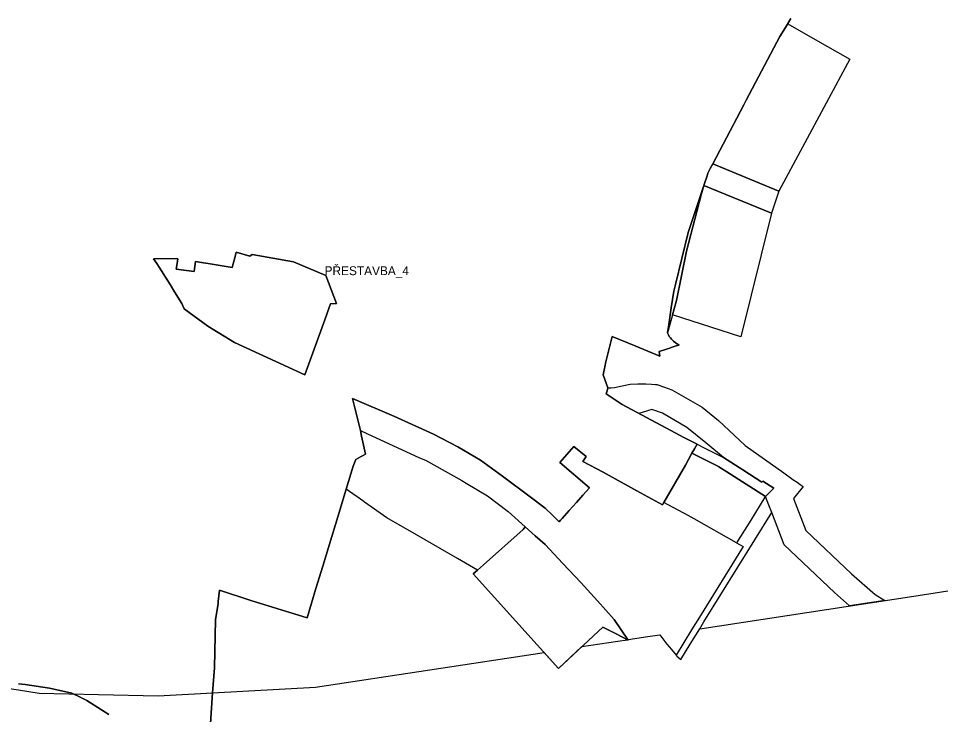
# Model space of a CAD drawing. Extents: x -521621 to -516761, y -1190184 to -1184927.
# Drawn here: x -518849 to -518120, y -1187593 to -1187044 of the extents above; entities that cross this region are included whole.
import ezdxf

# ---------------------------------------------------------------- set-up
doc = ezdxf.new("R2010")
doc.units = 0
for name, color, linetype in [('hran_SZUO_P-s', 7, 'Continuous'), ('HZU_P_s', 7, 'Continuous'), ('Implicitní', 7, 'Continuous'), ('prestavba_n', 7, 'Continuous'), ('zastavitelne plochy', 7, 'Continuous')]:
    doc.layers.add(name, color=color, linetype=linetype)

msp = doc.modelspace()

# ---------------------------------------------------------------- linework, layer by layer
at = {"layer": 'hran_SZUO_P-s'}
for points in [[(-518243.83, -1187051.46), (-518239.49, -1187044.29)], [(-518248.17, -1187058.62), (-518243.83, -1187051.46)], [(-518274.71, -1187108.86), (-518248.17, -1187058.62)], [(-518301.26, -1187159.09), (-518276.6, -1187112.43)], [(-518276.6, -1187112.43), (-518274.71, -1187108.86)], [(-518305.03, -1187166.24), (-518303.14, -1187162.67), (-518301.26, -1187159.09)], [(-518307.79, -1187174.55), (-518305.73, -1187168.34)], [(-518305.73, -1187168.34), (-518305.03, -1187166.24)], [(-518320.62, -1187213.04), (-518307.79, -1187174.55)], [(-518330.73, -1187254.09), (-518320.62, -1187213.04)], [(-518333.93, -1187272.52), (-518331.95, -1187259.37)], [(-518331.95, -1187259.37), (-518330.73, -1187254.09)], [(-518335.9, -1187285.67), (-518333.93, -1187272.52)], [(-518336.41, -1187289.03), (-518335.9, -1187285.67)], [(-518385.89, -1187316.34), (-518380.6, -1187295.26)], [(-518380.6, -1187295.26), (-518361.84, -1187302.95), (-518343.07, -1187310.63)], [(-518336.91, -1187292.39), (-518336.41, -1187289.03)], [(-518335.51, -1187295.27), (-518336.21, -1187293.83), (-518336.91, -1187292.39)], [(-518333.85, -1187297.41), (-518334.68, -1187296.34), (-518335.51, -1187295.27)], [(-518332.26, -1187298.84), (-518333.85, -1187297.41)], [(-518332.45, -1187303.46), (-518329.99, -1187302.65)], [(-518330.67, -1187300.27), (-518332.26, -1187298.84)], [(-518329.42, -1187301), (-518330.67, -1187300.27)], [(-518329.99, -1187302.65), (-518327.83, -1187301.94)], [(-518327.83, -1187301.94), (-518329.42, -1187301)], [(-518343.61, -1187307.03), (-518338.64, -1187305.49)], [(-518343.07, -1187310.63), (-518343.61, -1187307.03)], [(-518338.64, -1187305.49), (-518336.9, -1187304.92)], [(-518336.9, -1187304.92), (-518335.15, -1187304.35)], [(-518335.15, -1187304.35), (-518333.95, -1187303.95)], [(-518333.95, -1187303.95), (-518332.45, -1187303.46)], [(-518387.83, -1187325.37), (-518386.21, -1187317.82)], [(-518386.21, -1187317.82), (-518385.89, -1187316.34)], [(-518383.99, -1187335.74), (-518387.83, -1187325.37)], [(-518385.35, -1187340.38), (-518384.67, -1187338.06)], [(-518384.67, -1187338.06), (-518383.99, -1187335.74)], [(-518579.45, -1187369.29), (-518585.54, -1187344.09)], [(-518585.54, -1187344.09), (-518553.06, -1187357.95)], [(-518379.07, -1187344.6), (-518385.35, -1187340.38)], [(-518372.79, -1187348.81), (-518379.07, -1187344.6)], [(-518353.56, -1187359.03), (-518372.79, -1187348.81)], [(-518553.06, -1187357.95), (-518521.58, -1187372.14)], [(-518334.34, -1187369.25), (-518353.56, -1187359.03)], [(-518575.31, -1187388.01), (-518576.35, -1187383.33), (-518577.38, -1187378.65), (-518578.42, -1187373.97), (-518579.45, -1187369.29)], [(-518521.58, -1187372.14), (-518502.51, -1187382.22)], [(-518323.96, -1187374.76), (-518334.34, -1187369.25)], [(-518313.58, -1187380.27), (-518323.96, -1187374.76)], [(-518502.51, -1187382.22), (-518484.67, -1187392.87)], [(-518421.85, -1187394.65), (-518410.85, -1187382.12)], [(-518410.85, -1187382.12), (-518401.08, -1187389.94)], [(-518315.64, -1187383.75), (-518313.58, -1187380.27)], [(-518581.16, -1187391.1), (-518579.21, -1187390.07)], [(-518579.21, -1187390.07), (-518577.26, -1187389.04), (-518575.31, -1187388.01)], [(-518401.08, -1187389.94), (-518403.75, -1187393.75)], [(-518320.4, -1187392.2), (-518317.7, -1187387.23)], [(-518317.7, -1187387.23), (-518315.64, -1187383.75)], [(-518590.56, -1187415.7), (-518585.12, -1187397.38)], [(-518585.12, -1187397.38), (-518583.11, -1187392.13)], [(-518583.11, -1187392.13), (-518581.16, -1187391.1)], [(-518484.67, -1187392.87), (-518467.26, -1187405.28)], [(-518398.55, -1187414.52), (-518421.85, -1187394.65)], [(-518403.75, -1187393.75), (-518387.67, -1187402.29)], [(-518339.96, -1187426.08), (-518322.79, -1187396.6)], [(-518322.79, -1187396.6), (-518320.4, -1187392.2)], [(-518467.26, -1187405.28), (-518445.26, -1187421.79)], [(-518387.67, -1187402.29), (-518383.04, -1187404.83)], [(-518383.04, -1187404.83), (-518361.11, -1187416.86)], [(-518603.76, -1187459.07), (-518597.16, -1187437.39), (-518590.56, -1187415.7)], [(-518408.9, -1187426.17), (-518403.73, -1187420.34), (-518398.55, -1187414.52)], [(-518361.11, -1187416.86), (-518341.01, -1187427.89)], [(-518445.26, -1187421.79), (-518433.48, -1187430.64)], [(-518420.15, -1187438.82), (-518414.53, -1187432.5), (-518408.9, -1187426.17)], [(-518341.01, -1187427.89), (-518339.96, -1187426.08)], [(-518433.48, -1187430.64), (-518427.95, -1187436.01)], [(-518427.95, -1187436.01), (-518422.42, -1187441.37)], [(-518422.42, -1187441.37), (-518421.29, -1187440.09)], [(-518421.29, -1187440.09), (-518420.15, -1187438.82)], [(-518449.21, -1187445.4), (-518450.9, -1187447.42), (-518482.3, -1187475.38), (-518487.02, -1187479.58), (-518490.29, -1187482.49), (-518423, -1187557.03), (-518391.64, -1187528.05), (-518388.01, -1187524.58), (-518377.94, -1187529.66), (-518367.87, -1187534.73), (-518373.51, -1187526.55), (-518379.14, -1187518.37), (-518392.26, -1187503.79), (-518405.37, -1187489.2), (-518419.49, -1187474.31), (-518433.61, -1187459.42), (-518441.41, -1187452.41), (-518449.21, -1187445.4)], [(-518614.48, -1187493.95), (-518609.12, -1187476.51), (-518603.76, -1187459.07)], [(-518691.72, -1187504.38), (-518690.72, -1187495.41)], [(-518690.72, -1187495.41), (-518665.87, -1187503.51)], [(-518617.99, -1187505.53), (-518614.48, -1187493.95)], [(-518693.77, -1187518.41), (-518691.62, -1187506.18)], [(-518691.62, -1187506.18), (-518691.72, -1187504.38)], [(-518665.87, -1187503.51), (-518621.5, -1187517.1)], [(-518621.5, -1187517.1), (-518617.99, -1187505.53)], [(-518694.65, -1187556.56), (-518693.77, -1187518.41)], [(-518696.09, -1187576.42), (-518694.65, -1187556.56)], [(-518849.36, -1187569.22), (-518844.12, -1187569.84)], [(-518844.12, -1187569.84), (-518824.83, -1187572.77)], [(-518824.83, -1187572.77), (-518807.23, -1187576.63)], [(-518807.23, -1187576.63), (-518801.29, -1187579.56), (-518795.35, -1187582.49)], [(-518698.12, -1187604.41), (-518696.09, -1187576.42)], [(-518795.35, -1187582.49), (-518786.71, -1187587.97)], [(-518786.71, -1187587.97), (-518778.06, -1187593.45)]]:
    msp.add_lwpolyline(points, dxfattribs=at)
at = {"layer": 'HZU_P_s'}
for p, q in [((-518239.49, -1187044.29), (-518243.83, -1187051.46)), ((-518243.83, -1187051.46), (-518248.17, -1187058.62)), ((-518248.17, -1187058.62), (-518274.71, -1187108.86)), ((-518276.6, -1187112.43), (-518301.26, -1187159.09)), ((-518274.71, -1187108.86), (-518276.6, -1187112.43)), ((-518303.14, -1187162.67), (-518305.03, -1187166.24)), ((-518301.26, -1187159.09), (-518303.14, -1187162.67)), ((-518305.73, -1187168.34), (-518307.79, -1187174.55)), ((-518305.03, -1187166.24), (-518305.73, -1187168.34)), ((-518307.79, -1187174.55), (-518320.62, -1187213.04)), ((-518307.79, -1187174.55), (-518307.79, -1187174.55)), ((-518320.62, -1187213.04), (-518330.73, -1187254.09)), ((-518330.73, -1187254.09), (-518331.95, -1187259.37)), ((-518380.6, -1187295.26), (-518385.89, -1187316.34)), ((-518361.84, -1187302.95), (-518380.6, -1187295.26)), ((-518343.07, -1187310.63), (-518361.84, -1187302.95)), ((-518338.64, -1187305.49), (-518343.61, -1187307.03)), ((-518343.61, -1187307.03), (-518343.07, -1187310.63)), ((-518386.21, -1187317.82), (-518387.83, -1187325.37)), ((-518385.89, -1187316.34), (-518386.21, -1187317.82)), ((-518387.83, -1187325.37), (-518383.99, -1187335.74)), ((-518384.67, -1187338.06), (-518385.35, -1187340.38)), ((-518383.99, -1187335.74), (-518384.67, -1187338.06)), ((-518553.06, -1187357.95), (-518585.54, -1187344.09)), ((-518585.54, -1187344.09), (-518579.45, -1187369.29)), ((-518521.58, -1187372.14), (-518553.06, -1187357.95)), ((-518502.51, -1187382.22), (-518521.58, -1187372.14)), ((-518484.67, -1187392.87), (-518502.51, -1187382.22)), ((-518410.85, -1187382.12), (-518421.85, -1187394.65)), ((-518401.08, -1187389.94), (-518410.85, -1187382.12)), ((-518403.75, -1187393.75), (-518401.08, -1187389.94)), ((-518317.7, -1187387.23), (-518320.4, -1187392.2)), ((-518315.64, -1187383.75), (-518317.7, -1187387.23)), ((-518585.12, -1187397.38), (-518590.56, -1187415.7)), ((-518583.11, -1187392.13), (-518585.12, -1187397.38)), ((-518467.26, -1187405.28), (-518484.67, -1187392.87)), ((-518421.85, -1187394.65), (-518398.55, -1187414.52)), ((-518387.67, -1187402.29), (-518403.75, -1187393.75)), ((-518322.79, -1187396.6), (-518339.96, -1187426.08)), ((-518320.4, -1187392.2), (-518322.79, -1187396.6)), ((-518445.26, -1187421.79), (-518467.26, -1187405.28)), ((-518383.04, -1187404.83), (-518387.67, -1187402.29)), ((-518361.11, -1187416.86), (-518383.04, -1187404.83)), ((-518341.01, -1187427.89), (-518361.11, -1187416.86)), ((-518433.48, -1187430.64), (-518445.26, -1187421.79)), ((-518339.96, -1187426.08), (-518341.01, -1187427.89)), ((-518482.3, -1187475.38), (-518450.9, -1187447.42)), ((-518450.9, -1187447.42), (-518449.21, -1187445.4)), ((-518487.02, -1187479.58), (-518482.3, -1187475.38)), ((-518482.3, -1187475.38), (-518482.3, -1187475.38)), ((-518490.29, -1187482.49), (-518487.02, -1187479.58)), ((-518423, -1187557.03), (-518490.29, -1187482.49)), ((-518405.37, -1187489.2), (-518392.26, -1187503.79)), ((-518690.72, -1187495.41), (-518691.72, -1187504.38)), ((-518691.62, -1187506.18), (-518693.77, -1187518.41)), ((-518691.72, -1187504.38), (-518691.62, -1187506.18)), ((-518621.5, -1187517.1), (-518665.87, -1187503.51)), ((-518693.77, -1187518.41), (-518694.65, -1187556.56)), ((-518391.64, -1187528.05), (-518423, -1187557.03)), ((-518367.87, -1187534.73), (-518377.94, -1187529.66))]:
    msp.add_line(p, q, dxfattribs=at)
for points in [[(-518331.95, -1187259.37), (-518333.93, -1187272.52), (-518335.9, -1187285.67)], [(-518335.9, -1187285.67), (-518336.41, -1187289.03), (-518336.91, -1187292.39)], [(-518336.91, -1187292.39), (-518336.21, -1187293.83), (-518335.51, -1187295.27)], [(-518335.51, -1187295.27), (-518334.68, -1187296.34), (-518333.85, -1187297.41)], [(-518333.85, -1187297.41), (-518332.26, -1187298.84)], [(-518329.99, -1187302.65), (-518332.45, -1187303.46)], [(-518332.26, -1187298.84), (-518330.67, -1187300.27)], [(-518330.67, -1187300.27), (-518329.42, -1187301)], [(-518327.83, -1187301.94), (-518329.99, -1187302.65)], [(-518329.42, -1187301), (-518327.83, -1187301.94)], [(-518336.9, -1187304.92), (-518338.64, -1187305.49)], [(-518335.15, -1187304.35), (-518336.9, -1187304.92)], [(-518333.95, -1187303.95), (-518335.15, -1187304.35)], [(-518332.45, -1187303.46), (-518333.95, -1187303.95)], [(-518385.35, -1187340.38), (-518379.07, -1187344.6), (-518372.79, -1187348.81)], [(-518372.79, -1187348.81), (-518353.56, -1187359.03), (-518334.34, -1187369.25)], [(-518579.45, -1187369.29), (-518578.42, -1187373.97), (-518577.38, -1187378.65), (-518576.35, -1187383.33), (-518575.31, -1187388.01)], [(-518334.34, -1187369.25), (-518323.96, -1187374.76)], [(-518323.96, -1187374.76), (-518313.58, -1187380.27)], [(-518313.58, -1187380.27), (-518315.64, -1187383.75)], [(-518579.21, -1187390.07), (-518581.16, -1187391.1), (-518583.11, -1187392.13)], [(-518575.31, -1187388.01), (-518577.26, -1187389.04), (-518579.21, -1187390.07)], [(-518590.56, -1187415.7), (-518597.16, -1187437.39), (-518603.76, -1187459.07)], [(-518398.55, -1187414.52), (-518403.73, -1187420.34), (-518408.9, -1187426.17)], [(-518408.9, -1187426.17), (-518414.53, -1187432.5), (-518420.15, -1187438.82)], [(-518422.42, -1187441.37), (-518427.95, -1187436.01), (-518433.48, -1187430.64)], [(-518420.15, -1187438.82), (-518421.29, -1187440.09), (-518422.42, -1187441.37)], [(-518449.21, -1187445.4), (-518441.41, -1187452.41), (-518433.61, -1187459.42)], [(-518603.76, -1187459.07), (-518609.12, -1187476.51), (-518614.48, -1187493.95)], [(-518433.61, -1187459.42), (-518419.49, -1187474.31), (-518405.37, -1187489.2)], [(-518665.87, -1187503.51), (-518690.72, -1187495.41)], [(-518614.48, -1187493.95), (-518617.99, -1187505.53)], [(-518617.99, -1187505.53), (-518621.5, -1187517.1)], [(-518392.26, -1187503.79), (-518379.14, -1187518.37), (-518373.51, -1187526.55), (-518367.87, -1187534.73)], [(-518377.94, -1187529.66), (-518388.01, -1187524.58), (-518391.64, -1187528.05)], [(-518694.65, -1187556.56), (-518696.09, -1187576.42)], [(-518844.12, -1187569.84), (-518849.36, -1187569.22)], [(-518824.83, -1187572.77), (-518844.12, -1187569.84)], [(-518807.23, -1187576.63), (-518824.83, -1187572.77)], [(-518795.35, -1187582.49), (-518801.29, -1187579.56), (-518807.23, -1187576.63)], [(-518696.09, -1187576.42), (-518698.12, -1187604.41), (-518701.6, -1187652.25)], [(-518786.71, -1187587.97), (-518795.35, -1187582.49)], [(-518778.06, -1187593.45), (-518786.71, -1187587.97)]]:
    msp.add_lwpolyline(points, dxfattribs=at)
at = {"layer": 'Implicitní'}
for p, q in [((-518248.17, -1187058.62), (-518242.06, -1187048.54)), ((-518242.06, -1187048.54), (-518220.38, -1187060.82)), ((-518301.26, -1187159.09), (-518248.17, -1187058.62)), ((-518220.38, -1187060.82), (-518193.01, -1187076.32)), ((-518193.01, -1187076.32), (-518248.95, -1187180.44)), ((-518305.03, -1187166.24), (-518301.26, -1187159.09)), ((-518248.95, -1187180.44), (-518301.26, -1187159.09)), ((-518301.26, -1187159.09), (-518248.95, -1187180.44)), ((-518307.79, -1187174.55), (-518305.73, -1187168.34)), ((-518305.73, -1187168.34), (-518305.03, -1187166.24)), ((-518320.62, -1187213.04), (-518307.79, -1187174.55)), ((-518308.17, -1187176.14), (-518310.32, -1187183.32)), ((-518310.32, -1187183.32), (-518308.17, -1187176.14)), ((-518254.78, -1187197.93), (-518308.17, -1187176.14)), ((-518308.17, -1187176.14), (-518254.78, -1187197.93)), ((-518310.32, -1187183.32), (-518321.96, -1187227.97)), ((-518321.96, -1187227.97), (-518310.32, -1187183.32)), ((-518248.95, -1187180.44), (-518254.78, -1187197.93)), ((-518254.78, -1187197.93), (-518279.15, -1187295.59)), ((-518330.73, -1187254.09), (-518320.62, -1187213.04)), ((-518321.96, -1187227.97), (-518329.79, -1187266.69)), ((-518329.79, -1187266.69), (-518321.96, -1187227.97)), ((-518335.9, -1187285.67), (-518331.95, -1187259.37)), ((-518331.95, -1187259.37), (-518330.73, -1187254.09)), ((-518329.79, -1187266.69), (-518332.99, -1187278.06)), ((-518332.99, -1187278.06), (-518329.79, -1187266.69)), ((-518332.99, -1187278.06), (-518335.17, -1187285.8)), ((-518279.15, -1187295.59), (-518332.99, -1187278.06)), ((-518336.91, -1187292.39), (-518335.9, -1187285.67)), ((-518335.17, -1187285.8), (-518336.91, -1187292.39)), ((-518577.38, -1187378.65), (-518579.45, -1187369.29)), ((-518579.45, -1187369.29), (-518574.22, -1187371.72)), ((-518574.22, -1187371.72), (-518532.84, -1187390.9)), ((-518315.64, -1187383.75), (-518313.58, -1187380.27)), ((-518583.11, -1187392.13), (-518579.21, -1187390.07)), ((-518320.4, -1187392.2), (-518317.7, -1187387.23)), ((-518317.7, -1187387.23), (-518317.69, -1187387.22)), ((-518317.69, -1187387.22), (-518315.64, -1187383.75)), ((-518312.35, -1187389.9), (-518317.69, -1187387.22)), ((-518317.69, -1187387.22), (-518312.35, -1187389.9)), ((-518296.71, -1187397.76), (-518312.35, -1187389.9)), ((-518312.35, -1187389.9), (-518296.71, -1187397.76)), ((-518590.56, -1187415.7), (-518585.12, -1187397.38)), ((-518585.12, -1187397.38), (-518583.11, -1187392.13)), ((-518532.84, -1187390.9), (-518528.06, -1187392.9)), ((-518528.06, -1187392.9), (-518499.19, -1187408.92)), ((-518339.96, -1187426.08), (-518322.79, -1187396.6)), ((-518322.79, -1187396.6), (-518320.4, -1187392.2)), ((-518296.32, -1187398.01), (-518296.71, -1187397.76)), ((-518296.71, -1187397.76), (-518296.32, -1187398.01)), ((-518290.11, -1187401.98), (-518296.32, -1187398.01)), ((-518296.32, -1187398.01), (-518290.11, -1187401.98)), ((-518292.75, -1187390.8), (-518277.59, -1187400.47)), ((-518259.54, -1187421.48), (-518290.11, -1187401.98)), ((-518290.11, -1187401.98), (-518259.54, -1187421.48)), ((-518277.59, -1187400.47), (-518262.44, -1187410.14)), ((-518499.19, -1187408.92), (-518495.81, -1187410.8)), ((-518495.81, -1187410.8), (-518478.98, -1187420.84)), ((-518262.44, -1187410.14), (-518261.72, -1187409.41)), ((-518261.72, -1187409.41), (-518253.11, -1187414.91)), ((-518576.81, -1187425.41), (-518590.56, -1187415.7)), ((-518253.11, -1187414.91), (-518259.54, -1187421.48)), ((-518576.17, -1187425.86), (-518576.81, -1187425.41)), ((-518558.54, -1187438.31), (-518576.17, -1187425.86)), ((-518478.98, -1187420.84), (-518462.63, -1187433.34)), ((-518320.5, -1187436.54), (-518339.96, -1187426.08)), ((-518260.14, -1187422.08), (-518271.27, -1187440.02)), ((-518259.54, -1187421.48), (-518260.14, -1187422.08)), ((-518462.63, -1187433.34), (-518449.21, -1187445.4)), ((-518535.16, -1187451.58), (-518558.54, -1187438.31)), ((-518315.79, -1187439.19), (-518320.5, -1187436.54)), ((-518282.4, -1187457.96), (-518315.79, -1187439.19)), ((-518271.27, -1187440.02), (-518282.4, -1187457.96)), ((-518450.9, -1187447.42), (-518482.3, -1187475.38)), ((-518449.21, -1187445.4), (-518450.9, -1187447.42)), ((-518509.54, -1187466.48), (-518535.16, -1187451.58)), ((-518502.69, -1187470.47), (-518509.54, -1187466.48)), ((-518487.02, -1187479.58), (-518502.69, -1187470.47)), ((-518482.3, -1187475.38), (-518487.02, -1187479.58)), ((-518142.55, -1187500), (-518125.51, -1187497.4)), ((-518125.51, -1187497.4), (-518115.55, -1187495.89)), ((-518404.48, -1187539.91), (-518376.14, -1187535.59)), ((-518376.14, -1187535.59), (-518368.47, -1187534.43)), ((-518368.47, -1187534.43), (-518367.87, -1187534.73)), ((-518368.12, -1187534.37), (-518352.34, -1187531.97)), ((-518367.87, -1187534.73), (-518368.12, -1187534.37)), ((-518352.34, -1187531.97), (-518342.96, -1187530.54)), ((-518423, -1187557.03), (-518404.48, -1187539.91)), ((-518614.79, -1187571.96), (-518434.34, -1187544.46)), ((-518434.34, -1187544.46), (-518423, -1187557.03)), ((-518696.09, -1187576.42), (-518614.79, -1187571.96)), ((-518739.02, -1187578.77), (-518696.09, -1187576.42))]:
    msp.add_line(p, q, dxfattribs=at)
msp.add_lwpolyline([(-518678.32, -1187232.13), (-518677.41, -1187228.78), (-518666.6, -1187231.71), (-518664.87, -1187230.59), (-518632.31, -1187236.3), (-518606.69, -1187246.95), (-518598.4, -1187269.16), (-518603.01, -1187269.4), (-518604.06, -1187272.32), (-518607.59, -1187282.13), (-518623.21, -1187325.56), (-518678.91, -1187300.04), (-518699.82, -1187287), (-518718.5, -1187273.35), (-518720.29, -1187269.06), (-518726.08, -1187259.89), (-518729.6, -1187254.26), (-518740.03, -1187237.56), (-518742.72, -1187233.88), (-518724.88, -1187233.78), (-518723.56, -1187233.99), (-518724.18, -1187237.56), (-518724.98, -1187242.17), (-518710.78, -1187244.02), (-518709.7, -1187236.14), (-518703.41, -1187237.11), (-518699.71, -1187237.69), (-518680.63, -1187240.65)], close=True, dxfattribs=at)
for points in [[(-518259.54, -1187421.48), (-518253.87, -1187415.68), (-518253.11, -1187414.91), (-518261.72, -1187409.41), (-518262.44, -1187410.14), (-518277.59, -1187400.47), (-518292.75, -1187390.8), (-518306.58, -1187379.13), (-518321.66, -1187367.12), (-518340.92, -1187355.7), (-518349.21, -1187352.83), (-518359.49, -1187355.88), (-518372.79, -1187348.81), (-518379.07, -1187344.6), (-518385.35, -1187340.38), (-518384.97, -1187339.09), (-518384.67, -1187338.06), (-518383.99, -1187335.74), (-518381.4, -1187335.61), (-518378.81, -1187335.49), (-518372.64, -1187334.19), (-518366.47, -1187332.88), (-518360.28, -1187332.66), (-518354.09, -1187332.43), (-518349.56, -1187332.78), (-518346.44, -1187333.02), (-518345.02, -1187333.13), (-518344.51, -1187333.32), (-518339.29, -1187335.27), (-518333.55, -1187337.4), (-518309.69, -1187351.08), (-518296.66, -1187361.46), (-518275.69, -1187381.09), (-518245.02, -1187402.86), (-518237.86, -1187407.94), (-518234.69, -1187410.19)], [(-518579.21, -1187390.07), (-518575.31, -1187388.01), (-518577.38, -1187378.65)], [(-518313.58, -1187380.27), (-518308.55, -1187382.81), (-518300.65, -1187386.81), (-518292.75, -1187390.8)], [(-518234.69, -1187410.19), (-518232.24, -1187411.93), (-518229.8, -1187413.66)], [(-518229.8, -1187413.66), (-518237.49, -1187423.04), (-518227.74, -1187448.23), (-518191.68, -1187482.43), (-518172.9, -1187498.89), (-518165.48, -1187503.49), (-518193.17, -1187507.71), (-518205.16, -1187497.21), (-518244.77, -1187459.64), (-518254.65, -1187434.11)], [(-518254.65, -1187434.11), (-518256.92, -1187428.27), (-518259.54, -1187421.48)], [(-518342.96, -1187530.54), (-518337.35, -1187538.01), (-518333.78, -1187542.28), (-518330.21, -1187546.55), (-518329.85, -1187546.98), (-518329.48, -1187547.42), (-518327.99, -1187548.75), (-518326.5, -1187550.08), (-518319.01, -1187537.91), (-518311.51, -1187525.75), (-518142.55, -1187500)], [(-518865.68, -1187571.57), (-518849.4, -1187574.04), (-518833.12, -1187576.51)], [(-518833.12, -1187576.51), (-518786.07, -1187577.64), (-518739.02, -1187578.77)]]:
    msp.add_lwpolyline(points, dxfattribs=at)
at = {"layer": 'prestavba_n'}
msp.add_lwpolyline([(-518678.32, -1187232.13), (-518680.63, -1187240.65), (-518699.71, -1187237.69), (-518703.41, -1187237.11), (-518709.7, -1187236.14), (-518710.78, -1187244.02), (-518724.98, -1187242.17), (-518724.18, -1187237.56), (-518723.56, -1187233.99), (-518724.88, -1187233.78), (-518742.72, -1187233.88), (-518740.03, -1187237.56), (-518729.6, -1187254.26), (-518726.08, -1187259.89), (-518720.29, -1187269.06), (-518718.5, -1187273.35), (-518699.82, -1187287), (-518678.91, -1187300.04), (-518623.21, -1187325.56), (-518607.59, -1187282.13), (-518604.06, -1187272.32), (-518603.01, -1187269.4), (-518598.4, -1187269.16), (-518606.69, -1187246.95), (-518632.31, -1187236.3), (-518664.87, -1187230.59), (-518666.6, -1187231.71), (-518677.41, -1187228.78), (-518678.32, -1187232.13)], dxfattribs=at)
at = {"layer": 'zastavitelne plochy'}
msp.add_lwpolyline([(-518277.16, -1187460.9), (-518311.7, -1187516.56), (-518318.01, -1187526.74), (-518330.21, -1187546.55), (-518329.85, -1187546.98), (-518329.48, -1187547.42), (-518327.99, -1187548.75), (-518326.5, -1187550.08), (-518319.01, -1187537.91), (-518311.51, -1187525.75), (-518308.13, -1187520.29), (-518254.65, -1187434.11), (-518256.92, -1187428.27), (-518259.54, -1187421.48), (-518260.14, -1187422.08), (-518271.27, -1187440.02), (-518282.4, -1187457.96), (-518277.16, -1187460.9)], dxfattribs=at)

# ---------------------------------------------------------------- texts
at = {"layer": 'prestavba_n'}
msp.add_text('PŘESTAVBA_4', height=7, dxfattribs=at).set_placement((-518607.66, -1187246.8))

doc.saveas('drawing.dxf')
